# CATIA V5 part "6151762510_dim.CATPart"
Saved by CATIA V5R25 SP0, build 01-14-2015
Part number: 6151762510_dim
Source: made
Property "PROI_CREATED_ON": "12/17/2008 9:21:37 AM"
Property "BLANK_DRAWING": "--"
Property "DRAWN_BY": "FPA"
Property "FINISH": "--"
Property "HEAT_TREATMENT": "ASSIGN"
Property "MATERIAL": "ASSIGN"
Property "PROJECT": "--"
Property "PROTOTYPE_NO": "--"
Property "RELATED_DRAWING": "--"
Property "COMPLETE_MATERIAL": "ASSIGN-ASSIGN"
Property "DESCRIPTION": "XPBMC-6000"
Property "DRAWING_EXIST": "--"
Property "MANUFACTURER": "--"
Property "MANUFACTURER_2": "--"
Property "MANUFACTURER_REF": "--"
Property "TYPE_PART": "A"
Property "TODAY_DATE": "2024/11/08"
Property "PDMREV": "01.0"
Property "PDMRL": "Production"
Property "PROI_REVISION": "01"
Property "PROI_VERSION": "0"
Property "PROI_RELEASE": "Production"
Property "PTC_MODIFIED": false
Property "MFG_WP_MATERIAL": "ASSIGN"
Property "COMPANY_CODE": "---"
Property "DESCRIPTION_JP": "--"
Property "PQP_DOCUMENT": "--"
Property "SUPPLIER": "--"
Property "REFERENCE": "6151763440"
Property "PTC_WM_REVISION": "01"
Property "PTC_WM_ITERATION": "0"
Property "PTC_WM_VERSION": "01.0"
Property "PTC_WM_LIFECYCLE_STATE": "Production"
Property "PTC_WM_LIFECYCLE": "Design_Process"
Property "PTC_WM_LOCATION": "/Products/DRILLS TOOLS ASC/A1780 - XPB/9-01-Dimensional Drawings and 3D"
Property "PTC_WM_CREATED_BY": "Florian Pavageau (Grefpav) (Grefpav: CPD)"
Property "PTC_WM_CREATED_ON": "08-Nov-24 01:19:04 PM"
Property "PTC_WM_MODIFIED_BY": "Florian Pavageau (Grefpav) (Grefpav: CPD)"
Property "PTC_WM_MODIFIED_ON": "08-Nov-24 01:48:45 PM"
Property "PTC_WM_TEAM": "Default"
Property "PTC_ORGANIZATION_ID": "CPD"
Property "EXPORT_CONTROL": "NULL"
Property "PTC_WM_NAME": "6151762510_dim.prt"
Property "PTC_WM_NUMBER": "6151762510_DIM.PRT"
Property "PTC_COMMON_NAME": "6151762510_dim.prt"
Property "PTC_MASTER_MATERIAL": "ASSIGN"
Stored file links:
  d:\ptc\Echange\temp\6151762510_dim.CATPart

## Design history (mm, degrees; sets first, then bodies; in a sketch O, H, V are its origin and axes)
AxisSystem1 "CS0": origin (0, 0, 0), X (1, 0, 0), Y (0, 1, 0), Z (0, 0, 1)
Set1
  DatumSurface1 "Sheet.1"
  DatumSurface2 "Sheet.2"
  DatumSurface3 "Sheet.3"
  DatumSurface4 "Sheet.4"
  DatumSurface5 "Sheet.5"
  DatumSurface6 "Sheet.6"
  DatumSurface7 "Sheet.7"
  DatumSurface8 "Sheet.8"
  DatumSurface9 "Sheet.9"
  DatumSurface10 "Sheet.10"
  DatumSurface11 "Sheet.11"
  DatumSurface12 "Sheet.12"
  DatumSurface13 "Sheet.13"
  DatumSurface14 "Sheet.14"
  DatumSurface15 "Sheet.15"
  DatumSurface16 "Sheet.16"
  DatumSurface17 "Sheet.17"
  DatumSurface18 "Sheet.18"
  DatumSurface19 "Sheet.19"
  DatumSurface20 "Sheet.20"
  DatumSurface21 "Sheet.21"
  DatumSurface22 "Sheet.22"
  DatumSurface23 "Sheet.23"
  DatumSurface24 "Sheet.24"
  DatumSurface25 "Sheet.25"
  DatumSurface26 "Sheet.26"
  DatumSurface27 "Sheet.27"
  DatumSurface28 "Sheet.28"
  DatumSurface29 "Sheet.29"
  DatumSurface30 "Sheet.30"
  DatumSurface31 "Sheet.31"
  DatumSurface32 "Sheet.32"
  DatumSurface33 "Sheet.33"
  DatumSurface34 "Sheet.34"
  DatumSurface35 "Sheet.35"
  DatumSurface36 "Sheet.36"
  DatumSurface37 "Sheet.37"
  DatumSurface38 "Sheet.38"
  DatumSurface39 "Sheet.39"
  DatumSurface40 "Sheet.40"
  DatumSurface41 "Sheet.41"
  DatumSurface42 "Sheet.42"
  Plane1 "RIGHT": stored without definition
  Plane2 "TOP": stored without definition
  Plane3 "FRONT": stored without definition
Body1 "PartBody" (main body)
